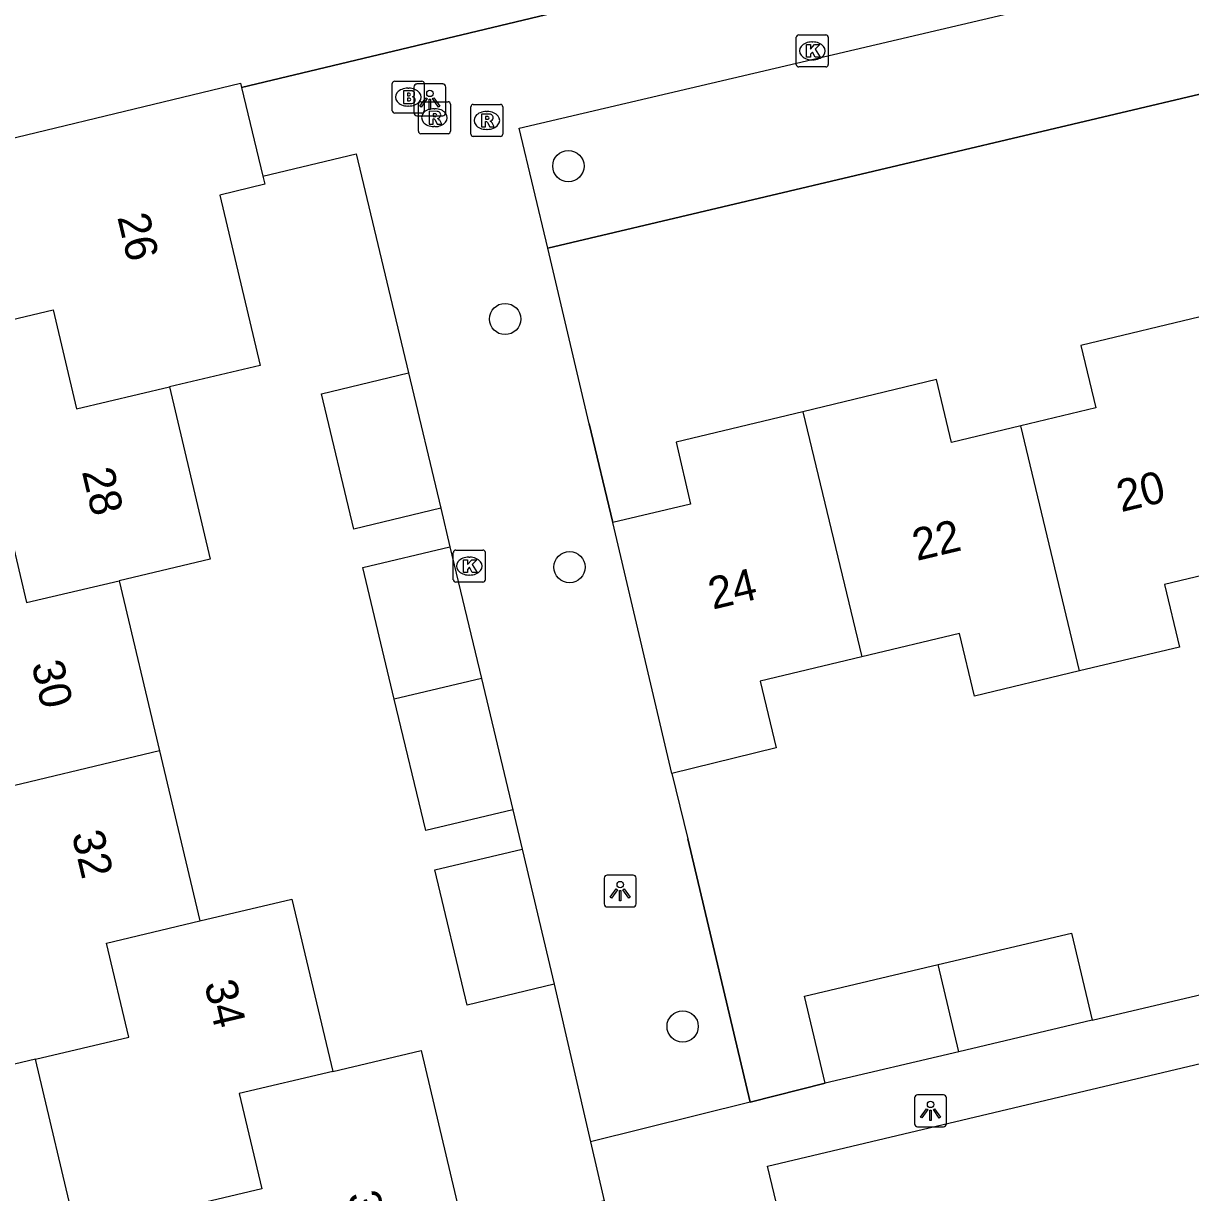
# Model space of a CAD drawing. Extents: x 158038 to 159242, y 380133 to 381214.
# Drawn here: x 158558.46 to 158594.98, y 380505 to 380541.6 of the extents above; entities that cross this region are included whole.
import ezdxf

# ---------------------------------------------------------------- set-up
doc = ezdxf.new("R2010")
doc.units = 0
for name, color, linetype in [('IMGEO_Boom', 7, 'Continuous'), ('IMGEO_Brandkraan', 7, 'Continuous'), ('IMGEO_Groenvoorziening', 7, 'Continuous'), ('IMGEO_Hek', 7, 'Continuous'), ('IMGEO_Kolk', 7, 'Continuous'), ('IMGEO_Lichtpunt', 7, 'Continuous'), ('IMGEO_Muur', 7, 'Continuous'), ('IMGEO_Pand', 7, 'Continuous'), ('IMGEO_Pand_nummerreeks', 7, 'Continuous'), ('IMGEO_Rioolput', 7, 'Continuous'), ('IMGEO_Voetpad_open', 7, 'Continuous')]:
    doc.layers.add(name, color=color, linetype=linetype)

msp = doc.modelspace()

# ---------------------------------------------------------------- linework, layer by layer
at = {"layer": 'IMGEO_Boom'}
for centre in [(158575.514, 380537.132), (158573.534, 380532.345), (158575.552, 380524.579), (158579.089, 380510.203)]:
    msp.add_circle(centre, 0.489, dxfattribs=at)
at = {"layer": 'IMGEO_Brandkraan'}
for p, q in [((158570.006, 380538.864), (158570.006, 380539.716)), ((158570.081, 380539.79), (158570.933, 380539.79)), ((158570.494, 380539.57), (158570.519, 380539.57)), ((158571.007, 380539.716), (158571.007, 380538.864)), ((158570.933, 380538.79), (158570.081, 380538.79)), ((158570.517, 380539.01), (158570.492, 380539.01))]:
    msp.add_line(p, q, dxfattribs=at)
for points in [[(158570.006, 380538.864), (158570.006, 380539.716)], [(158570.081, 380539.79), (158570.933, 380539.79)], [(158570.354, 380539.49), (158570.354, 380539.09), (158570.567, 380539.09)], [(158570.585, 380539.49), (158570.354, 380539.49)], [(158571.007, 380539.716), (158571.007, 380538.864)], [(158570.533, 380539.409), (158570.479, 380539.409), (158570.479, 380539.333)], [(158570.479, 380539.333), (158570.532, 380539.333)], [(158570.541, 380539.257), (158570.479, 380539.257), (158570.479, 380539.176)], [(158570.479, 380539.176), (158570.541, 380539.176)], [(158570.933, 380538.79), (158570.081, 380538.79)]]:
    msp.add_lwpolyline(points, dxfattribs=at)
for centre, radius, start, end in [((158570.083, 380539.714), 0.0765, 91.552, 178.448), ((158570.083, 380539.714), 0.0765, 91.552, 178.448), ((158570.589, 380539.345), 0.145, 59.4692, 91.5367), ((158570.614, 380539.392), 0.0922, 285.5137, 58.1501), ((158570.931, 380539.714), 0.0765, 1.552, 88.448), ((158570.931, 380539.714), 0.0765, 1.552, 88.448), ((158570.534, 380539.371), 0.0379, 267.8285, 90.9355), ((158570.542, 380539.216), 0.0404, 269.8759, 90.5077), ((158570.573, 380539.341), 0.251, 268.6676, 293.5347), ((158570.619, 380539.2), 0.105, 301.3115, 78.989), ((158570.083, 380538.866), 0.0765, 181.552, 268.448), ((158570.083, 380538.866), 0.0765, 181.552, 268.448), ((158570.931, 380538.866), 0.0765, 271.552, 358.448), ((158570.931, 380538.866), 0.0765, 271.552, 358.448)]:
    msp.add_arc(centre, radius, start, end, dxfattribs=at)
for centre, major_axis, ratio, start_param, end_param in [((158570.493, 380539.29), (-0.387, 0.002), 0.722429, 4.712389, 7.853982), ((158570.518, 380539.29), (-0.39, 0.002), 0.717154, 1.570796, 4.712389)]:
    msp.add_ellipse(centre, major_axis=major_axis, ratio=ratio, start_param=start_param, end_param=end_param, dxfattribs=at)
at = {"layer": 'IMGEO_Groenvoorziening'}
msp.add_lwpolyline([(158613.195, 380543.627), (158574.87, 380534.558)], dxfattribs=at)
at = {"layer": 'IMGEO_Hek'}
for points in [[(158581.954, 380543.586), (158565.287, 380539.592)], [(158574.87, 380534.558), (158613.195, 380543.627)], [(158576.163, 380529.062), (158574.87, 380534.558)]]:
    msp.add_lwpolyline(points, dxfattribs=at)
at = {"layer": 'IMGEO_Kolk'}
for p, q in [((158582.645, 380540.311), (158582.645, 380541.163)), ((158582.72, 380541.237), (158583.572, 380541.237)), ((158583.133, 380541.017), (158583.158, 380541.017)), ((158583.646, 380541.163), (158583.646, 380540.311)), ((158583.572, 380540.237), (158582.72, 380540.237)), ((158583.156, 380540.457), (158583.131, 380540.457)), ((158571.915, 380524.185), (158571.915, 380525.037)), ((158571.99, 380525.111), (158572.842, 380525.111)), ((158572.403, 380524.891), (158572.428, 380524.891)), ((158572.916, 380525.037), (158572.916, 380524.185)), ((158572.842, 380524.111), (158571.99, 380524.111)), ((158572.426, 380524.331), (158572.401, 380524.331))]:
    msp.add_line(p, q, dxfattribs=at)
for points in [[(158582.645, 380540.311), (158582.645, 380541.163)], [(158582.72, 380541.237), (158583.572, 380541.237)], [(158582.966, 380540.937), (158583.089, 380540.937), (158583.089, 380540.786), (158583.219, 380540.937), (158583.383, 380540.937), (158583.237, 380540.786), (158583.39, 380540.537), (158583.238, 380540.537), (158583.153, 380540.701), (158583.089, 380540.634), (158583.089, 380540.537), (158582.966, 380540.537), (158582.966, 380540.937)], [(158583.646, 380541.163), (158583.646, 380540.311)], [(158583.572, 380540.237), (158582.72, 380540.237)], [(158571.915, 380524.185), (158571.915, 380525.037)], [(158571.99, 380525.111), (158572.842, 380525.111)], [(158572.916, 380525.037), (158572.916, 380524.185)], [(158572.236, 380524.811), (158572.359, 380524.811), (158572.359, 380524.66), (158572.489, 380524.811), (158572.653, 380524.811), (158572.507, 380524.66), (158572.66, 380524.411), (158572.508, 380524.411), (158572.423, 380524.575), (158572.359, 380524.508), (158572.359, 380524.411), (158572.236, 380524.411), (158572.236, 380524.811)], [(158572.842, 380524.111), (158571.99, 380524.111)]]:
    msp.add_lwpolyline(points, dxfattribs=at)
for centre, start, end in [((158582.722, 380541.161), 91.552, 178.448), ((158582.722, 380541.161), 91.552, 178.448), ((158583.57, 380541.161), 1.552, 88.448), ((158583.57, 380541.161), 1.552, 88.448), ((158582.722, 380540.313), 181.552, 268.448), ((158582.722, 380540.313), 181.552, 268.448), ((158583.57, 380540.313), 271.552, 358.448), ((158583.57, 380540.313), 271.552, 358.448), ((158571.992, 380525.035), 91.552, 178.448), ((158571.992, 380525.035), 91.552, 178.448), ((158572.84, 380525.035), 1.552, 88.448), ((158572.84, 380525.035), 1.552, 88.448), ((158571.992, 380524.187), 181.552, 268.448), ((158571.992, 380524.187), 181.552, 268.448), ((158572.84, 380524.187), 271.552, 358.448), ((158572.84, 380524.187), 271.552, 358.448)]:
    msp.add_arc(centre, 0.0765, start, end, dxfattribs=at)
for centre, major_axis, ratio, start_param, end_param in [((158583.132, 380540.737), (-0.387, 0.002), 0.722429, 4.712389, 7.853982), ((158583.157, 380540.737), (-0.39, 0.002), 0.717154, 1.570796, 4.712389), ((158572.402, 380524.611), (-0.387, 0.002), 0.722429, 4.712389, 7.853982), ((158572.427, 380524.611), (-0.39, 0.002), 0.717154, 1.570796, 4.712389)]:
    msp.add_ellipse(centre, major_axis=major_axis, ratio=ratio, start_param=start_param, end_param=end_param, dxfattribs=at)
at = {"layer": 'IMGEO_Lichtpunt'}
for p, q in [((158570.682, 380539.606), (158570.682, 380538.799)), ((158570.682, 380539.606), (158570.682, 380538.799)), ((158571.584, 380539.701), (158570.776, 380539.701)), ((158571.584, 380539.701), (158570.776, 380539.701)), ((158571.678, 380538.799), (158571.678, 380539.606)), ((158571.678, 380538.799), (158571.678, 380539.606)), ((158570.776, 380538.705), (158571.584, 380538.705)), ((158570.776, 380538.705), (158571.584, 380538.705)), ((158576.636, 380514.844), (158576.636, 380514.037)), ((158576.636, 380514.844), (158576.636, 380514.037)), ((158577.538, 380514.939), (158576.73, 380514.939)), ((158577.538, 380514.939), (158576.73, 380514.939)), ((158577.632, 380514.037), (158577.632, 380514.844)), ((158577.632, 380514.037), (158577.632, 380514.844)), ((158576.73, 380513.943), (158577.538, 380513.943)), ((158576.73, 380513.943), (158577.538, 380513.943)), ((158587.248, 380508.057), (158586.44, 380508.057)), ((158587.248, 380508.057), (158586.44, 380508.057)), ((158586.346, 380507.962), (158586.346, 380507.155)), ((158586.346, 380507.962), (158586.346, 380507.155)), ((158587.342, 380507.155), (158587.342, 380507.962)), ((158587.342, 380507.155), (158587.342, 380507.962)), ((158586.44, 380507.061), (158587.248, 380507.061)), ((158586.44, 380507.061), (158587.248, 380507.061))]:
    msp.add_line(p, q, dxfattribs=at)
for points in [[(158571.056, 380539.27), (158571.095, 380539.242), (158570.907, 380538.98), (158570.869, 380539.007), (158571.056, 380539.27)], [(158571.158, 380539.222), (158571.205, 380539.222), (158571.205, 380538.9), (158571.158, 380538.9), (158571.158, 380539.222)], [(158571.268, 380539.242), (158571.306, 380539.269), (158571.493, 380539.007), (158571.454, 380538.979), (158571.268, 380539.242)], [(158577.01, 380514.508), (158577.049, 380514.48), (158576.861, 380514.218), (158576.823, 380514.245), (158577.01, 380514.508)], [(158577.112, 380514.46), (158577.159, 380514.46), (158577.159, 380514.138), (158577.112, 380514.138), (158577.112, 380514.46)], [(158577.222, 380514.48), (158577.26, 380514.507), (158577.447, 380514.245), (158577.408, 380514.217), (158577.222, 380514.48)], [(158586.72, 380507.626), (158586.759, 380507.598), (158586.571, 380507.336), (158586.533, 380507.363), (158586.72, 380507.626)], [(158586.822, 380507.578), (158586.869, 380507.578), (158586.869, 380507.256), (158586.822, 380507.256), (158586.822, 380507.578)], [(158586.932, 380507.598), (158586.97, 380507.625), (158587.157, 380507.363), (158587.118, 380507.335), (158586.932, 380507.598)]]:
    msp.add_lwpolyline(points, dxfattribs=at)
for centre in [(158571.181, 380539.404), (158577.135, 380514.642), (158586.845, 380507.76)]:
    msp.add_circle(centre, 0.0994, dxfattribs=at)
for centre, start, end in [((158570.776, 380539.606), 90, 180), ((158570.776, 380539.606), 90, 180), ((158571.584, 380539.606), 0, 90), ((158571.584, 380539.606), 0, 90), ((158570.776, 380538.799), 180, 270), ((158570.776, 380538.799), 180, 270), ((158571.584, 380538.799), 270, 0), ((158571.584, 380538.799), 270, 360), ((158576.73, 380514.844), 90, 180), ((158576.73, 380514.844), 90, 180), ((158577.538, 380514.844), 0, 90), ((158577.538, 380514.844), 0, 90), ((158576.73, 380514.037), 180, 270), ((158576.73, 380514.037), 180, 270), ((158577.538, 380514.037), 270, 0), ((158577.538, 380514.037), 270, 360), ((158586.44, 380507.962), 90, 180), ((158586.44, 380507.962), 90, 180), ((158587.248, 380507.962), 0, 90), ((158587.248, 380507.962), 0, 90), ((158586.44, 380507.155), 180, 270), ((158586.44, 380507.155), 180, 270), ((158587.248, 380507.155), 270, 0), ((158587.248, 380507.155), 270, 360)]:
    msp.add_arc(centre, 0.0946, start, end, dxfattribs=at)
at = {"layer": 'IMGEO_Muur'}
for points in [[(158576.163, 380529.062), (158576.905, 380525.979)], [(158583.547, 380508.424), (158581.201, 380507.836), (158579.253, 380516.079)]]:
    msp.add_lwpolyline(points, dxfattribs=at)
at = {"layer": 'IMGEO_Pand'}
for points in [[(158556.494, 380531.943), (158555.223, 380537.31), (158565.254, 380539.731), (158565.287, 380539.592)], [(158565.287, 380539.592), (158565.957, 380536.819)], [(158565.957, 380536.819), (158566.018, 380536.563), (158564.607, 380536.222), (158565.868, 380530.893), (158563.035, 380530.223)], [(158556.494, 380531.943), (158559.398, 380532.631), (158560.13, 380529.536), (158563.035, 380530.223)], [(158595.542, 380532.475), (158591.549, 380531.518), (158592.017, 380529.565), (158589.666, 380529.001)], [(158571.525, 380526.419), (158568.802, 380525.767), (158567.786, 380530.004), (158570.509, 380530.656)], [(158570.509, 380530.656), (158571.525, 380526.419)], [(158589.666, 380529.001), (158587.499, 380528.482), (158587.028, 380530.448), (158582.85, 380529.444)], [(158563.035, 380530.223), (158564.312, 380524.828), (158561.465, 380524.154)], [(158582.85, 380529.444), (158578.884, 380528.492), (158579.34, 380526.551), (158576.905, 380525.979)], [(158582.85, 380529.444), (158584.692, 380521.773)], [(158591.508, 380521.328), (158589.666, 380529.001)], [(158554.949, 380525.809), (158557.849, 380526.495), (158558.565, 380523.468), (158561.465, 380524.154)], [(158578.752, 380518.124), (158576.905, 380525.979)], [(158570.068, 380520.447), (158569.087, 380524.564), (158571.81, 380525.214)], [(158571.81, 380525.214), (158572.792, 380521.097)], [(158597.384, 380524.804), (158594.168, 380524.033), (158594.637, 380522.078), (158591.508, 380521.328)], [(158561.465, 380524.154), (158562.725, 380518.83)], [(158591.508, 380521.328), (158588.218, 380520.54), (158587.747, 380522.505), (158584.692, 380521.773)], [(158584.692, 380521.773), (158581.519, 380521.012), (158582.019, 380518.923), (158578.752, 380518.124)], [(158572.792, 380521.097), (158570.068, 380520.447)], [(158572.792, 380521.097), (158573.774, 380516.98)], [(158573.774, 380516.98), (158571.05, 380516.33), (158570.068, 380520.447)], [(158562.725, 380518.83), (158556.885, 380517.432)], [(158562.725, 380518.83), (158563.985, 380513.504)], [(158558.839, 380509.174), (158555.981, 380508.498), (158554.83, 380513.364), (158554.63, 380514.207), (158557.489, 380514.883), (158556.885, 380517.432)], [(158575.073, 380511.521), (158572.35, 380510.871), (158571.341, 380515.099), (158574.065, 380515.749)], [(158574.065, 380515.749), (158575.073, 380511.521)], [(158563.985, 380513.504), (158566.865, 380514.186), (158568.141, 380508.794)], [(158558.839, 380509.174), (158561.761, 380509.865), (158561.063, 380512.812), (158563.985, 380513.504)], [(158587.081, 380512.136), (158591.258, 380513.124), (158591.902, 380510.399)], [(158583.547, 380508.424), (158582.903, 380511.149), (158587.081, 380512.136)], [(158587.725, 380509.411), (158587.081, 380512.136)], [(158591.902, 380510.399), (158587.725, 380509.411)], [(158562.972, 380504.423), (158560.123, 380503.749), (158558.839, 380509.174)], [(158568.141, 380508.794), (158570.904, 380509.448), (158572.219, 380503.889), (158573.728, 380504.249), (158573.771, 380504.068)], [(158587.725, 380509.411), (158583.547, 380508.424)], [(158568.141, 380508.794), (158565.216, 380508.102), (158565.921, 380505.121), (158562.972, 380504.423)]]:
    msp.add_lwpolyline(points, dxfattribs=at)
at = {"layer": 'IMGEO_Rioolput'}
for p, q in [((158570.898, 380539.146), (158571.75, 380539.146)), ((158570.823, 380538.22), (158570.823, 380539.072)), ((158571.311, 380538.926), (158571.336, 380538.926)), ((158571.824, 380539.072), (158571.824, 380538.22)), ((158572.463, 380538.134), (158572.463, 380538.986)), ((158572.538, 380539.06), (158573.39, 380539.06)), ((158572.951, 380538.84), (158572.976, 380538.84)), ((158573.464, 380538.986), (158573.464, 380538.134)), ((158571.75, 380538.146), (158570.898, 380538.146)), ((158571.334, 380538.366), (158571.309, 380538.366)), ((158573.39, 380538.06), (158572.538, 380538.06)), ((158572.974, 380538.28), (158572.949, 380538.28))]:
    msp.add_line(p, q, dxfattribs=at)
for points in [[(158570.898, 380539.146), (158571.75, 380539.146)], [(158570.823, 380538.22), (158570.823, 380539.072)], [(158571.412, 380538.844), (158571.16, 380538.846), (158571.16, 380538.446)], [(158571.338, 380538.765), (158571.284, 380538.765), (158571.284, 380538.684)], [(158571.824, 380539.072), (158571.824, 380538.22)], [(158572.463, 380538.134), (158572.463, 380538.986)], [(158572.538, 380539.06), (158573.39, 380539.06)], [(158573.052, 380538.758), (158572.8, 380538.76), (158572.8, 380538.36)], [(158573.464, 380538.986), (158573.464, 380538.134)], [(158571.16, 380538.446), (158571.284, 380538.446), (158571.284, 380538.608), (158571.295, 380538.608)], [(158571.284, 380538.684), (158571.336, 380538.684)], [(158571.342, 380538.579), (158571.413, 380538.446), (158571.553, 380538.446), (158571.488, 380538.572)], [(158572.8, 380538.36), (158572.924, 380538.36), (158572.924, 380538.522), (158572.935, 380538.522)], [(158572.978, 380538.679), (158572.924, 380538.679), (158572.924, 380538.598)], [(158572.924, 380538.598), (158572.976, 380538.598)], [(158572.982, 380538.493), (158573.053, 380538.36), (158573.193, 380538.36), (158573.128, 380538.486)], [(158571.75, 380538.146), (158570.898, 380538.146)], [(158573.39, 380538.06), (158572.538, 380538.06)]]:
    msp.add_lwpolyline(points, dxfattribs=at)
for centre, radius, start, end in [((158570.9, 380539.07), 0.0765, 91.552, 178.448), ((158570.9, 380539.07), 0.0765, 91.552, 178.448), ((158571.748, 380539.07), 0.0765, 1.552, 88.448), ((158571.748, 380539.07), 0.0765, 1.552, 88.448), ((158571.344, 380538.669), 0.0964, 77.0061, 93.1865), ((158571.358, 380538.726), 0.0378, 276.6634, 79.6772), ((158571.411, 380538.734), 0.109, 350.3612, 89.416), ((158572.54, 380538.984), 0.0765, 91.552, 178.448), ((158572.54, 380538.984), 0.0765, 91.552, 178.448), ((158573.051, 380538.648), 0.109, 350.3612, 89.416), ((158573.388, 380538.984), 0.0765, 1.552, 88.448), ((158573.388, 380538.984), 0.0765, 1.552, 88.448), ((158571.294, 380538.555), 0.0533, 26.0293, 88.6989), ((158571.32, 380538.873), 0.19, 274.7715, 282.9687), ((158571.409, 380538.734), 0.112, 277.5842, 350.9817), ((158571.393, 380538.519), 0.108, 29.5134, 73.7905), ((158572.934, 380538.469), 0.0533, 26.0293, 88.6989), ((158572.96, 380538.787), 0.19, 274.7715, 282.9687), ((158572.984, 380538.583), 0.0964, 77.0061, 93.1865), ((158572.998, 380538.64), 0.0378, 276.6634, 79.6772), ((158573.049, 380538.648), 0.112, 277.5842, 350.9817), ((158573.033, 380538.433), 0.108, 29.5134, 73.7905), ((158570.9, 380538.222), 0.0765, 181.552, 268.448), ((158570.9, 380538.222), 0.0765, 181.552, 268.448), ((158571.748, 380538.222), 0.0765, 271.552, 358.448), ((158571.748, 380538.222), 0.0765, 271.552, 358.448), ((158572.54, 380538.136), 0.0765, 181.552, 268.448), ((158572.54, 380538.136), 0.0765, 181.552, 268.448), ((158573.388, 380538.136), 0.0765, 271.552, 358.448), ((158573.388, 380538.136), 0.0765, 271.552, 358.448)]:
    msp.add_arc(centre, radius, start, end, dxfattribs=at)
for centre, major_axis, ratio, start_param, end_param in [((158571.31, 380538.646), (-0.387, 0.002), 0.722429, 4.712389, 7.853982), ((158571.335, 380538.646), (-0.39, 0.002), 0.717154, 1.570796, 4.712389), ((158572.95, 380538.56), (-0.387, 0.002), 0.722429, 4.712389, 7.853982), ((158572.975, 380538.56), (-0.39, 0.002), 0.717154, 1.570796, 4.712389)]:
    msp.add_ellipse(centre, major_axis=major_axis, ratio=ratio, start_param=start_param, end_param=end_param, dxfattribs=at)
at = {"layer": 'IMGEO_Voetpad_open'}
for points in [[(158574.87, 380534.558), (158573.976, 380538.315), (158612.332, 380547.323), (158613.195, 380543.627)], [(158565.287, 380539.592), (158581.954, 380543.586)], [(158565.957, 380536.819), (158568.877, 380537.519), (158570.509, 380530.656)], [(158576.905, 380525.979), (158576.163, 380529.062), (158574.87, 380534.558)], [(158571.525, 380526.419), (158571.81, 380525.214)], [(158578.752, 380518.124), (158579.253, 380516.079), (158581.201, 380507.836)], [(158573.774, 380516.98), (158574.065, 380515.749)], [(158582.453, 380502.891), (158581.739, 380505.83), (158620.043, 380514.915), (158620.771, 380511.94)], [(158575.073, 380511.521), (158576.21, 380506.585)], [(158591.902, 380510.399), (158596.234, 380511.423)], [(158581.201, 380507.836), (158583.547, 380508.424)], [(158581.201, 380507.836), (158576.21, 380506.585)], [(158576.21, 380506.585), (158576.633, 380504.746), (158573.771, 380504.068)]]:
    msp.add_lwpolyline(points, dxfattribs=at)

# ---------------------------------------------------------------- texts
at = {"layer": 'IMGEO_Pand_nummerreeks'}
for s, rotation, p in [('26', 283.3139, (158561.399, 380535.537)), ('28', 283.3169, (158560.291, 380527.572)), ('20', 13.4325, (158592.807, 380526.296)), ('22', 13.4325, (158586.415, 380524.77)), ('24', 13.4325, (158580.032, 380523.246)), ('30', 283.3149, (158558.713, 380521.538)), ('32', 283.3101, (158559.972, 380516.219)), ('34', 283.3139, (158564.121, 380511.539)), ('36', 283.3127, (158568.602, 380504.931))]:
    msp.add_text(s, height=1, rotation=rotation, dxfattribs=at).set_placement(p)

doc.saveas('drawing.dxf')
